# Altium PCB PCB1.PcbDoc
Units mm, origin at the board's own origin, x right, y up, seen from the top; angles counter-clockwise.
Board outline 100 x 80 mm, 2 copper layers (Top Layer, Bottom Layer); 38 components, 32 nets, 175 pads, 63 vias.
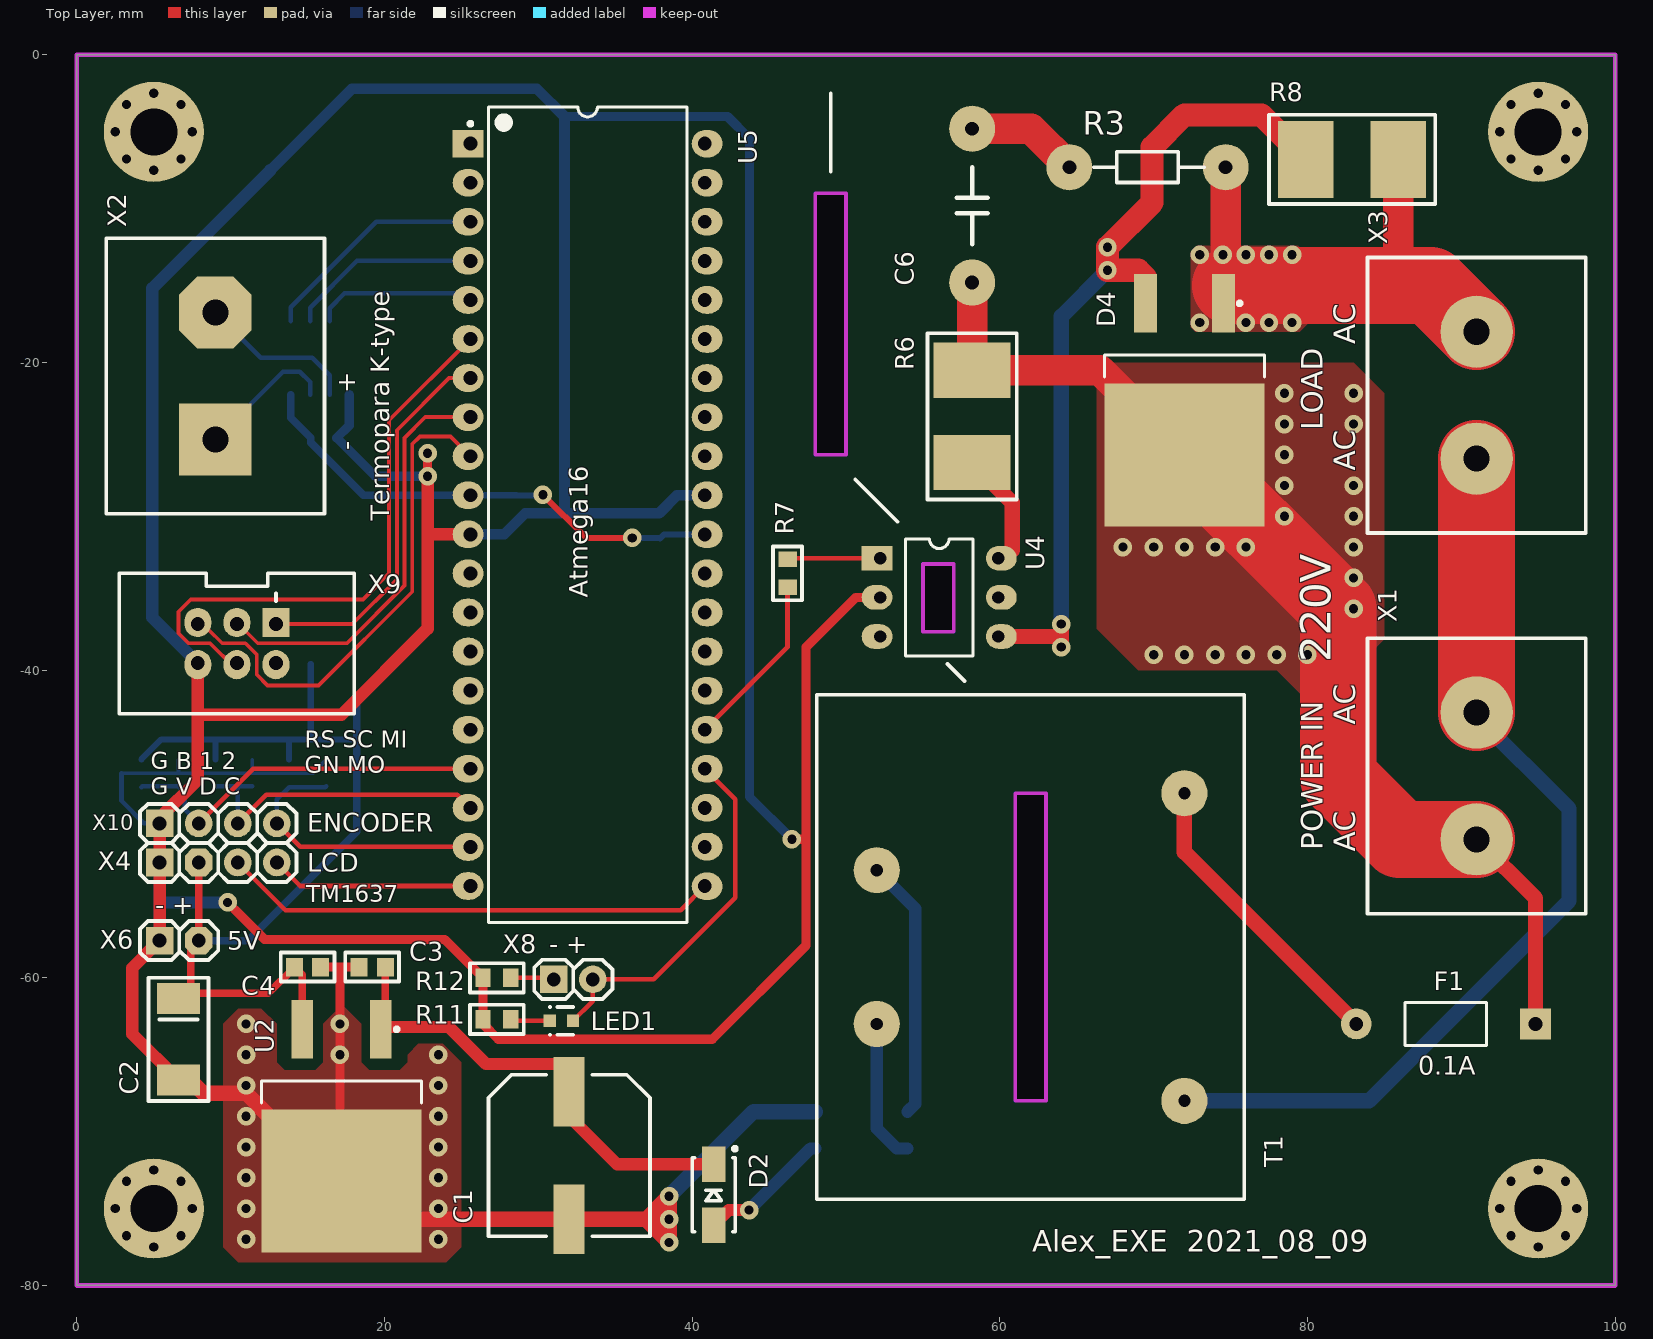
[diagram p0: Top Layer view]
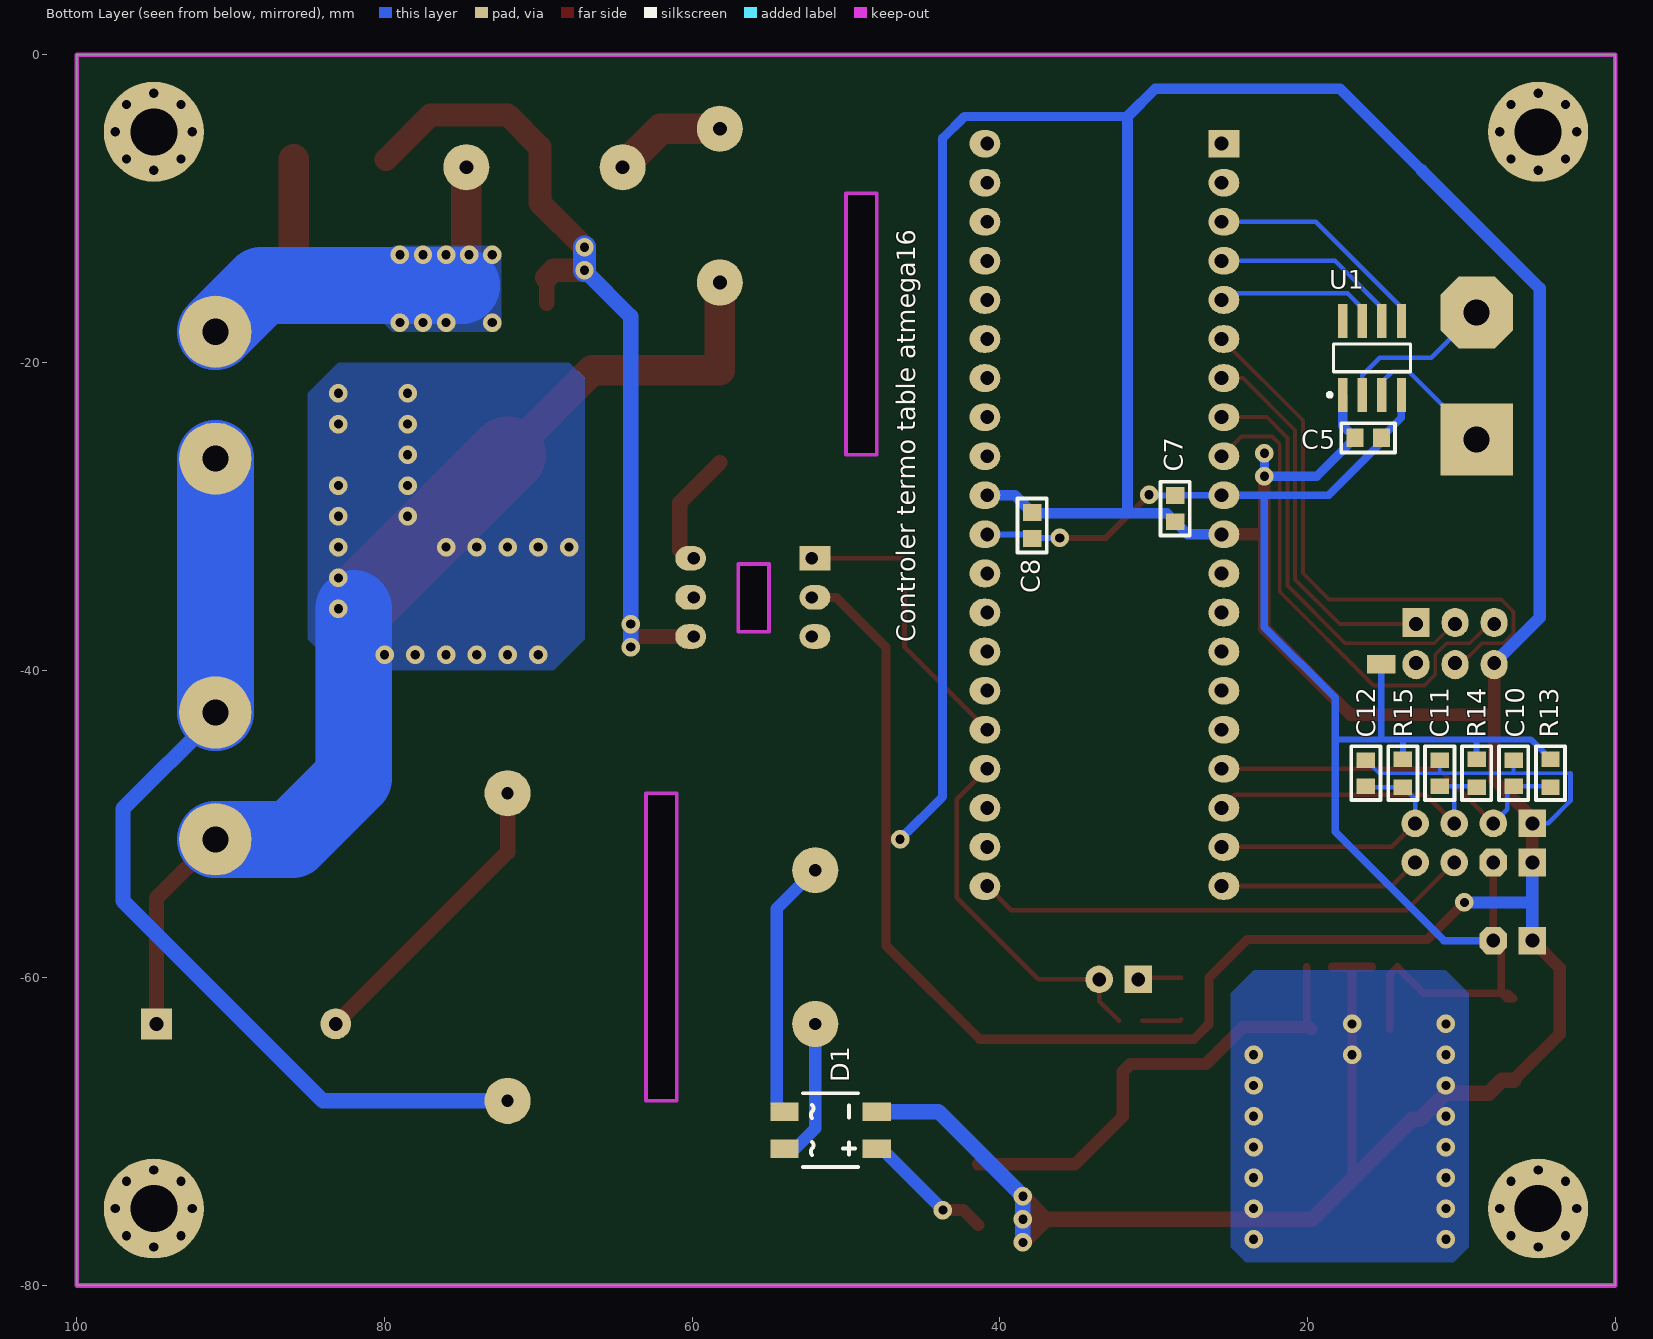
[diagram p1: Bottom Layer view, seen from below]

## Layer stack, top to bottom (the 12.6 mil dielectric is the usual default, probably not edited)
Top Solder: solder mask 0.0102, Solder Resist, Dk 3.5
Top Layer: signal copper 0.0356
Dielectric 1: dielectric 0.32, FR-4, Dk 4.8
Bottom Layer: signal copper 0.0356
Bottom Solder: solder mask 0.0102, Solder Resist, Dk 3.5

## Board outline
0,-80 0,0 100,0 100,-80
cut-out: 48,-9 50,-9 50,-26 48,-26
cut-out: 55,-33.1 57,-33.1 57,-37.5 55,-37.5
cut-out: 61,-48 63,-48 63,-68 61,-68

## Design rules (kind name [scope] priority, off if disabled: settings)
BoardOutlineClearance [All] p1: gap=0.8 ignorepadtopadclearanceinfootprint=FALSE
Clearance [All] p1: gap=0.25 ignorepadtopadclearanceinfootprint=FALSE
ComponentClearance ComponentClearance_x4_x9 [InComponent('X4') or InComponent('X9')] p1: gap=-1 collisioncheckmode=3 verticalgap=2540 showdistances=FALSE
ComponentClearance [All] p2: gap=0.254 collisioncheckmode=3 verticalgap=0.254 showdistances=FALSE
HoleSize HoleSize_via [IsVia] p1: absolutevalues=TRUE maxlimit=1 minlimit=0.5 maxpercent=80.000 minpercent=20.000
HoleSize [All] p2: absolutevalues=TRUE maxlimit=5 minlimit=0.6 maxpercent=80.000 minpercent=20.000
MinimumAnnularRing [All] p1: minimumring=0.3
MinimumSolderMaskSliver [All] p1: minsoldermaskwidth=0.24
PolygonConnect [All] p1: connectstyle=Direct reliefconductorwidth=0.254 reliefentries=4 polygonreliefangle="90 Angle" airgapwidth=0.254
RoomDefinition Sheet1 [InComponentClass('Sheet1')] p1: confinementstyle=ConfineIn formatcopy=TRUE lockcomponents=FALSE outline -58,-116 408,-116 408,80 -58,80
RoutingVias [All] p1: holewidth=0.6 width=1.2 viastyle="Through Hole" minholewidth=0.5 minwidth=1.2 maxholewidth=1 maxwidth=1.5
SilkToSilkClearance [All] p1: silktosilkclearance=0.24
SilkToSolderMaskClearance [IsPad] p1: minsilkscreentomaskgap=0.18 clearancetoexposedcopper=TRUE
SolderMaskExpansion [All] p1: expansion=0.08 istentingtop=FALSE
Width [All] p1: maxlimit=5 minlimit=0.25 preferedwidth=0.3
25 further rules are at their usual default settings.

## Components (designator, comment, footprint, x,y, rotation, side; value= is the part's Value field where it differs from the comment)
C1 "470uF" CAP-SMD-10.5 32,-75.7 r0 top
C2 "100uF" Tantal_C 6.6,-64 r270 top
C3 "0.1uF" CAP-0603#1 19.2,-59.3 r0 top
C4 "0.1uF" CAP-0603#1 15,-59.3 r180 top
C5 "0.1uF" CAP-0603#1 16.05,-24.9 r180 bottom
C6 "0.01uF" К73-17-630 58.2,-9.8 r270 top
C7 "0.1uF" CAP-0603#1 28.6,-29.5 r90 bottom
C8 "0.1uF" CAP-0603#1 37.9,-30.6 r270 bottom
C10 "0.1uF" CAP-0603#2 6.6,-46.7 r270 bottom
C11 "0.1uF" CAP-0603#2 11.4,-46.7 r270 bottom
C12 "0.1uF" CAP-0603#2 16.2,-46.7 r270 bottom
D1 "MB1S" MBS 51,-69.9 r270 bottom
D2 "SS16" SMA 41.4,-74.1 r270 top
D4 "BT136B-600E,118" TO-263_N#1 72,-22.45 r270 top
F1 "0.1A" PIN-W2/E2.8 89,-63 r180 top
LED1 "LED_LOAD" "LED0603 - red" 31.5,-62.8 r180 top
R3 "47" "resistor 0.125W 10.16mm" 69.6,-7.3 r0 top
R6 "360" res-2512 58.2,-23.5 r90 top
R7 "470" RES-0603 46.2,-33.7 r90 top
R8 "360" res-2512 82.9,-6.8 r0 top
R11 "1K" RES-0603 27.3,-62.7 r0 top
R12 "1K" RES-0603 27.3,-60 r180 top
R13 "47K" RES-0603 4.2,-46.7 r90 bottom
R14 "47K" RES-0603 9,-46.7 r90 bottom
R15 "47K" RES-0603 13.8,-46.7 r90 bottom
T1 "Trans" "BV EI Schema 1" 62,-58 r180 top
U1 "MAX31855EASA+" MAXM-S8+4_N 15.8,-19.7 r90 bottom
U2 "L7805ABD2T-TR" TO-263_N#2 17.2,-69.65 r270 top
U4 "MOC3061" DIP6 52.22,-32.73 r0 top
U5 "ATmega16-16PU" 40P6 33.2,-29.9 r0 top
X1 "KF35C-8.25-02P" KF35C-8.25-02P#1 91,-51 r90 top
X2 "KF35C-8.25-02P" KF35C-8.25-02P#2 9,-25 r90 top
X3 "KF35C-8.25-02P" KF35C-8.25-02P#1 91,-26.25 r90 top
X4 "PLS4" PLS4#1 5.38,-52.5 r0 top
X6 "PLS2" PLS2#1 5.38,-57.58 r0 top
X8 "PLS2" PLS2#2 31,-60.1 r0 top
X9 "IDC6M" IDC6M 12.94,-37 r180 top
X10 "PLS4" PLS4#2 5.38,-49.96 r0 top

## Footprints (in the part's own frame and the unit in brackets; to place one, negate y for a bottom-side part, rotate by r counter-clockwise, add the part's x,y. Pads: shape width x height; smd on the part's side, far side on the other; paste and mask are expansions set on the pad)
40P6 [mm] "40-Pin Ceramic Dual In-Line Package (CerDIP)"
  rect 2x1.8 hole 0.9 copper offset -0.15,0: 1(-7.62,24.13)
  oval 2x1.8 hole 0.9 copper offset -0.15,0: 2(-7.62,21.59) 3(-7.62,19.05) 4(-7.62,16.51) 5(-7.62,13.97) 6(-7.62,11.43) 7(-7.62,8.89) 8(-7.62,6.35) 9(-7.62,3.81) 10(-7.62,1.27) 11(-7.62,-1.27) 12(-7.62,-3.81) 13(-7.62,-6.35) 14(-7.62,-8.89) 15(-7.62,-11.43) 16(-7.62,-13.97) 17(-7.62,-16.51) 18(-7.62,-19.05) 19(-7.62,-21.59) 20(-7.62,-24.13)
  oval 2x1.8 hole 0.9 copper offset 0.15,-0.02: 21(7.62,-24.13)
  oval 2x1.8 hole 0.9 copper offset 0.15,0.02: 22(7.62,-21.59)
  oval 2x1.8 hole 0.9 copper offset 0.15,0: 23(7.62,-19.05) 24(7.62,-16.51) 25(7.62,-13.97) 26(7.62,-11.43) 27(7.62,-8.89) 28(7.62,-6.35) 29(7.62,-3.81) 30(7.62,-1.27) 31(7.62,1.27) 32(7.62,3.81) 33(7.62,6.35) 34(7.62,8.89) 35(7.62,11.43) 36(7.62,13.97) 37(7.62,16.51) 38(7.62,19.05) 39(7.62,21.59) 40(7.62,24.13)
  silkscreen extent -7.74,-26.5 6.45,26.5, body extent -7.05,-26.47 7.05,26.47, height 4.83
"BV EI Schema 1" [mm]
  round 3 hole 0.8: 1(-10,-10) 5(-10,10) 7(10,5) 9(10,-5)
  silkscreen extent -13.9,-16.4 13.9,16.4, body extent -13.9,-16.4 13.9,16.4, height 21.8
CAP-0603#1 [mm]
  rect 1.1x1.2 smd: 1(-0.85,0) 2(0.85,0)
  silkscreen extent -1.75,-0.95 1.75,0.95, body extent -0.85,-0.4 0.75,0.4, height 0.9
CAP-0603#2 [mm]
  rect 1x1.2 smd: 1(-0.85,0) 2(0.85,0)
  silkscreen extent -1.75,-0.95 1.75,0.95, body extent -0.85,-0.4 0.75,0.4, height 0.9
CAP-SMD-10.5 [mm]
  rect 2x4.5 smd: 1(0,8.3) 2(0,0)
  silkscreen extent -5.25,-1.1 5.25,9.4, body extent -5.25,-1.1 5.25,9.4, height 10.8
DIP6 [mm]
  rect 2x1.6 hole 0.8 copper offset -0.2,0: 1(0,0)
  oval 2x1.6 hole 0.8 copper offset -0.2,0: 2(0,-2.54) 3(0,-5.08)
  oval 2x1.6 hole 0.8 copper offset 0.2,0: 4(7.68,-5.08) 5(7.68,-2.54) 6(7.68,0)
  silkscreen extent 1.63,-6.35 6.05,1.27, body extent 1.45,-6.1 6.2,1, height 3.6
IDC6M [mm]
  rect 1.75x1.9 hole 0.9 copper offset 0,-0.1: 1(0,0)
  oval 1.75x1.9 hole 0.9 copper offset 0,0.1: 2(0,2.54) 4(2.54,2.54) 6(5.08,2.54)
  oval 1.75x1.9 hole 0.9 copper offset 0,-0.1: 3(2.54,0) 5(5.08,0)
  silkscreen extent -5.1,-3.3 10.18,5.84, body extent -5.1,-3.3 10.18,5.84, height 9
KF35C-8.25-02P#1 [mm]
  round 4.7 hole 1.7: 1(0,0) 2(8.25,0)
  silkscreen extent -4.83,-7.1 13.08,7.1, body extent -4.73,-7.05 12.97,7.05, height 15.1
KF35C-8.25-02P#2 [mm]
  rect 4.7x4.7 hole 1.7: 1(0,0)
  oct 4.7x4.7 hole 1.7: 2(8.25,0)
  silkscreen extent -4.83,-7.1 13.08,7.1, body extent -4.73,-7.05 12.97,7.05, height 15.1
"LED0603 - red" [mm]
  rect 0.8x0.8 smd: 1(-0.75,0) 2(0.75,0)
  silkscreen extent -0.75,-0.9 0.75,0.9, body extent -0.8,-0.4 0.8,0.4, height 0.8
MAXM-S8+4_N [mm] "SOIC, 8-Leads, Body 4.9x3.9mm, Pitch 1.27mm, IPC Medium Density"
  rect 2.2x0.6 smd: 1(-2.4,1.905) 2(-2.4,0.635) 3(-2.4,-0.635) 4(-2.4,-1.905) 5(2.4,-1.905) 6(2.4,-0.635) 7(2.4,0.635) 8(2.4,1.905)
  silkscreen extent -2.52,-2.5 0.9,2.88, body extent -2,-2.5 2,2.5, height 1.75
MBS [mm]
  rect 1.2x1.84 smd: 1(1.2,3) 2(-1.2,3) 3(-1.2,-3) 4(1.2,-3)
  silkscreen extent -2.4,-1.8 2.4,1.8, body extent -2.4,-3.5 2.4,3.5, height 3.05
PIN-W2/E2.8 [mm] "Thru-Hole; 2 Leads"
  rect 2x2 hole 0.9: 1(-5.825,0)
  round 2 hole 0.9: 2(5.825,0)
  silkscreen extent -2.65,-1.4 2.65,1.4
PLS2#1 [mm]
  rect 1.8x1.8 hole 0.9: 1(0,0)
  oct 1.8x1.8 hole 0.9: 2(2.54,0)
  silkscreen extent -1.27,-1.27 3.81,1.27, body extent -1.27,-1.27 3.81,1.27, height 8.5
PLS2#2 [mm]
  rect 1.8x1.8 hole 0.9: 1(0,0)
  round 1.8 hole 0.9: 2(2.54,0)
  silkscreen extent -1.27,-1.27 3.81,1.27, body extent -1.27,-1.27 3.81,1.27, height 8.5
PLS4#1 [mm]
  rect 1.8x1.8 hole 0.9: 1(0,0)
  oct 1.8x1.8 hole 0.9: 2(2.54,0)
  round 1.8 hole 0.9: 3(5.08,0) 4(7.62,0)
  silkscreen extent -1.27,-1.27 8.89,1.27, body extent -1.27,-1.27 8.89,1.27, height 8.5
PLS4#2 [mm]
  rect 1.8x1.8 hole 0.9: 1(0,0)
  round 1.8 hole 0.9: 2(2.54,0) 3(5.08,0) 4(7.62,0)
  silkscreen extent -1.27,-1.27 8.89,1.27, body extent -1.27,-1.27 8.89,1.27, height 8.5
RES-0603 [mm]
  rect 1x1.2 smd: 1(-0.9,0) 2(0.9,0)
  silkscreen extent -1.75,-0.95 1.75,0.95, body extent -0.85,-0.4 0.75,0.4, height 0.45
res-2512 [mm]
  rect 3.6x5 smd: 1(-3,0) 2(3,0)
  silkscreen extent -5.4,-2.9 5.4,2.9, body extent -3.2,-1.6 3.15,1.6, height 0.55
"resistor 0.125W 10.16mm" [mm] "resistor 0.125W 10.16mm"
  round 3 hole 0.9: 1(-5.08,0) 2(5.08,0)
  silkscreen extent -3.5,-1 3.68,1, body extent -5.18,-1 5.18,1, height 2.99
SMA [mm] "Molded Diode, 2-Leads, Body 4,50x2,60mm, IPC Medium Density"
  rect 2.3x1.55 smd: 1(-1.975,0) 2(1.975,0)
  silkscreen extent -3.12,-1.4 2.4,1.5, body extent -2.3,-1.35 2.3,1.35, height 2.1
Tantal_C [mm]
  rect 2x2.8 smd: 1(-2.65,0) 2(2.65,0)
  silkscreen extent -4,-1.95 4,1.95, body extent -3,-1.6 3,1.6, height 2.5
TO-263_N#1 [mm] "D2-PAK, 4-Leads, Body 9.2x10.2mm, Pitch 2.54mm, Lead Span 15.4mm, IPC Medium Density"
  rect 3.8x1.5 smd: 1(-6.3,2.54) 3(-6.3,-2.54)
  rect 9.3x10.4 smd: 4(3.55,0)
  silkscreen extent -6.42,-5.2 -1.5,5.2, body extent -2.95,-5.2 6.4,5.2, height 4.6
TO-263_N#2 [mm] "D2-PAK, 4-Leads, Body 9.2x10.2mm, Pitch 2.54mm, Lead Span 15.4mm, IPC Medium Density"
  rect 3.8x1.4 smd: 1(-6.3,2.54) 3(-6.3,-2.54)
  rect 9.3x10.4 smd: 4(3.55,0)
  silkscreen extent -6.42,-5.2 -1.5,5.2, body extent -2.95,-5.2 6.4,5.2, height 4.6
К73-17-630 [mm]
  round 3 hole 0.9: 1(-5,0) 2(5,0)
  silkscreen extent -2.5,-1 2.5,1, body extent -6,-3 6,3, height 12

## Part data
C1: library part "Cap Pol", "Polarized Capacitor (Axial)", Voltage=25V
C2: library part "Cap Pol", "Polarized Capacitor (Axial)", Voltage=16V
C3 C4 C5 C6 C7 C8 C10 C11 C12: library part Cap, "Capacitor", Voltage=25V
D1: library part Bridge1, "Full Wave Diode Bridge"
D2: library part "D Schottky", "Schottky Diode"
D4: library part BTA12-600C4G, "Triacs, Silicon Bidirectional Thyristor, 3-Pin TO-220, Pb-Free, Tube", Manufacturer="On Semiconductor"
F1: library part "Fuse 1", "Fuse"
LED1: library part LED0, "Typical INFRARED GaAs LED", Color=RED
R3 R6 R7 R8 R11 R12 R13 R14 R15: library part Res
T1: "Transformer"
U1: "Cold Junction Compensated Thermocouple to Digital Converter, 14 Bits Temperature Resolution, -40 to 125 degC, 8-Pin SOIC (S8+4), Pb-Free", Generic Part Number=MAX31855, Supplier Part Number 1=MAX31855EASA+-ND
U2: "Positive Voltage Regulator, 3-Pin D2PAK, Tape and Reel"
U4: library part MOC3021SM, "Опто транзистор x1 5.3kV 70V 0.05A"
U5: "8-bit AVR Microcontroller, 4.5-5.5V, 16KB Flash, 512 Bytes EEPROM, 1KB SRAM, 40-pin PDIP, Industrial Grade (-40°C to 85°C), Pb-Free"
X1 X2 X3: library part PLS2

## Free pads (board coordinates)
  round 6.5 hole 3.05 unplated: 1(5,-75) 1(5,-5) 1(95,-75) 1(95,-5)
  round 1.2 hole 0.6 mask+0.08: 2(2.5,-75) 2(2.5,-5) 2(3.232,-76.768) 2(3.232,-73.232) 2(3.232,-6.768) 2(3.232,-3.232) 2(5,-77.5) 2(5,-72.5) 2(5,-7.5) 2(5,-2.5) 2(6.768,-76.768) 2(6.768,-73.232) 2(6.768,-6.768) 2(6.768,-3.232) 2(7.5,-75) 2(7.5,-5) 2(92.5,-75) 2(92.5,-5) 2(93.232,-76.768) 2(93.232,-73.232) 2(93.232,-6.768) 2(93.232,-3.232) 2(95,-77.5) 2(95,-72.5) 2(95,-7.5) 2(95,-2.5) 2(96.768,-76.768) 2(96.768,-73.232) 2(96.768,-6.768) 2(96.768,-3.232) 2(97.5,-75) 2(97.5,-5)
  rect 1.84x1.2 smd far side: 11(15.2,-39.6)

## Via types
v1: diameter 1.2, hole 0.6, Top Layer to Bottom Layer, tented both sides, 63 vias

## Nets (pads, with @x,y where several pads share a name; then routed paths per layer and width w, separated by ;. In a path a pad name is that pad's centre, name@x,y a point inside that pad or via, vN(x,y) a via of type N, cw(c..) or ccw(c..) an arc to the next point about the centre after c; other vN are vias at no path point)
EN_1: C11.2 R14.1 U5.18 X10.3 | length 21.1
  Top Layer w0.3: X10.3 12.32,-48.1 24.73,-48.1 U5.18
  Bottom Layer w0.3: R14.1 9.05,-47.55 10.46,-47.55 ; X10.3 10.46,-47.55 ; C11.2 10.46,-47.55
EN_2: C12.2 R15.1 U5.19 X10.4 | length 18.3
  Top Layer w0.3: X10.4 14.53,-51.49 U5.19
  Bottom Layer w0.3: X10.4 13,-48.4 R15.1 16.15,-47.6 C12.2
EN_B: C10.2 R13.1 U5.17 X10.2 | length 24.5
  Top Layer w0.3: X10.2 11.47,-46.41 U5.17
  Bottom Layer w0.3: R13.1 4.25,-47.55 C10.2 7,-47.95 7,-49.04 X10.2
GND: C1.2 C2.2 C3.1 C4.1 C5.1 C7.1 C8.1 C10.1 C11.1 C12.1 D1.2 R11.1 R12.2 U1.1 U2.4 U4.2 U5.11 U5.31 X4.1 X6.1 X9.6 X10.1 | length 408.2
  Top Layer w0.6: 10.25,-55.55 12.2,-57.5 23.9,-57.5 R12.2 R11.1 26.4,-63 27.4,-64 41.3,-64 47.4,-57.9 47.4,-51 ; C4.1 17.1,-59.3 ; U2.4 17.1,-73.1 v1(17.1,-65) v1(17.1,-63) 17.1,-59.3 ; C3.1 17.1,-59.3 ; v1(22.8,-27.4) v1(22.8,-25.9) ; v1(46.485,-50.985) 47.385,-50.985 47.4,-51 ; U4.2 50.63,-35.27 47.4,-38.5 47.4,-51
  Top Layer w0.8: C2.2 3.6,-63.65 3.6,-59.36 X6.1 X4.1 X10.1 5.38,-49.62 7.86,-47.14 7.86,-42.9 ; X9.6 7.86,-42.9 ; v1(22.8,-27.4) 22.8,-31.17 ; U5.11 22.8,-31.17 ; 7.86,-42.9 17.2,-42.9 22.8,-37.3 22.8,-31.17
  Top Layer w1: C2.2 7.35,-66.65 8.2,-67.5 11,-67.5 12.7,-69.2 13.2,-69.2 U2.4@17.1,-73.1 ; U2.4 19.7,-75.7 C1.2 37,-75.7 ; 37,-75.7 v1(38.5,-74.2) v1(38.5,-75.7) ; 37,-75.7 v1(38.5,-77.2) v1(38.5,-75.7) ; 37,-75.7 v1(38.5,-75.7)
  Bottom Layer w0.25: 2.9,-46.7 6.6,-46.7 ; C10.1 6.6,-46.7 ; C11.1 11.4,-46.7 ; C12.1 15.35,-46.7 11.4,-46.7 ; 6.6,-46.7 11.4,-46.7
  Bottom Layer w0.3: 2.9,-46.7 2.9,-48.5 4.36,-49.96 X10.1
  Bottom Layer w0.6: U1.1 17.705,-24.095 C5.1 19.4,-27.4 v1(22.8,-27.4) v1(22.8,-25.9) ; 31.7,-4 42.3,-4 43.72,-5.42 43.72,-30.98 43.72,-48.22 v1(46.485,-50.985)
  Bottom Layer w0.7: 12.58,-7.5 17.88,-2.2 29.9,-2.2 31.7,-4 31.7,-29.8 ; U5.11 27.78,-31.17 C7.1 29.15,-29.8 31.7,-29.8 ; U5.31 39.02,-28.63 C8.1 37.85,-29.8 31.7,-29.8
  Bottom Layer w0.8: X6.1 5.38,-55.1 ; X4.1 5.38,-55.1 ; X9.6 4.9,-36.58 4.9,-15.18 12.58,-7.5 ; v1(9.8,-55.1) 5.38,-55.1
  Bottom Layer w1: v1(38.5,-77.2) v1(38.5,-75.7) v1(38.5,-74.2) 44,-68.7 D1.2
  other v1: 11,-77 23.5,-77 11,-75 23.5,-75 11,-73 23.5,-73 11,-71 23.5,-71 11,-69 23.5,-69 11,-67 23.5,-67 11,-65 23.5,-65 11,-63
L_CLK: U5.20 X4.4 | length 13.2
  Top Layer w0.3: X4.4 14.53,-54.03 U5.20
L_DIO: U5.21 X4.3 | length 32.3
  Top Layer w0.3: X4.3 13.56,-55.6 39.25,-55.6 U5.21
LED_LOAD: LED1.1 U5.24 X8.2 | length 23.9
  Top Layer w0.3: LED1.1 33.54,-61.51 X8.2 37.5,-60.1 42.799,-54.801 42.799,-52.901 42.8,-52.9 42.8,-48.39 U5.24
LOAD_ON: R7.1 U5.25 | length 11.5
  Top Layer w0.3: U5.25 46.2,-38.49 R7.1
MISO: U5.7 X9.1 | length 24.9
  Top Layer w0.25: X9.1 17.9,-37 20.8,-34.1 20.8,-24.4 24.19,-21.01 U5.7
MOSI: U5.6 X9.4 | length 38.3
  Top Layer w0.25: X9.4 10.17,-39.77 8.65,-38.25 7.25,-38.25 6.6,-37.6 6.6,-36.2 7.4,-35.4 18.6,-35.4 20.3,-33.7 20.3,-23.75 U5.6
NetC1_1: C1.1 C3.2 D2.1 U2.1 | length 31.3
  Top Layer w0.5: U2.1 20.05,-63.04 C3.2
  Top Layer w0.8: U2.1 19.89,-63.2 24.2,-63.2 26.6,-65.6 31.5,-65.6 32,-66.1 C1.1 32,-69 35.125,-72.125 D2.1
NetC6_1: C6.1 R3.1 | length 7.4
  Top Layer w2: C6.1 62.02,-4.8 R3.1
NetC6_2: C6.2 D4.4 F1.1 R6.2 X1.1 | length 93.4
  Top Layer w1: D4.4 D4.4@72,-25.4 ; X1.1 94.825,-54.825 F1.1
  Top Layer w2: C6.2 R6.2 66.5,-20.5 D4.4
  Top Layer w5: D4.4 81.5,-35.5 82,-36 82,-47 86,-51 X1.1
  Bottom Layer w5: 82,-36 82,-47 86,-51 X1.1
  other v1: 70,-39 72,-39 74,-39 76,-39 78,-39 80,-39 83,-36 83,-34 68,-32 70,-32 72,-32 74,-32 76,-32 83,-32 78.5,-30 83,-30 78.5,-28 83,-28 78.5,-26 78.5,-24 83,-24 78.5,-22 83,-22
NetD1_1: D1.1 D2.2 | length 8.7
  Top Layer w0.8: D2.2 42.375,-75.1 v1(43.7,-75.1)
  Bottom Layer w0.8: v1(43.7,-75.1) 47.7,-71.1 D1.1
NetD1_3: D1.3 T1.9 | length 16.9
  Bottom Layer w0.8: T1.9 54.5,-55.5 54.5,-60.4 54.5,-68.2 D1.3
NetD1_4: D1.4 T1.7 | length 9.4
  Bottom Layer w0.6: D1.4 D1.4@54.05,-71.15
  Bottom Layer w0.8: T1.7 52,-69.8 53.3,-71.1 D1.4
NetD4_1: D4.1 R3.2 R8.2 X3.2 | length 51.4
  Top Layer w1: 85.9,-12.9 88,-15
  Top Layer w2: R3.2 74.68,-14.68 D4.1@75,-15 ; 85.9,-12.9 R8.2
  Top Layer w5: D4.1@75,-15 88,-15 X3.2
  Bottom Layer w5: 75,-15 88,-15 X3.2
  other v1: 73,-17.4 76,-17.4 77.5,-17.4 79,-17.4 73,-13 74.5,-13 76,-13 77.5,-13 79,-13
NetD4_3: D4.3 R8.1 U4.4 | length 58.5
  Top Layer w1: U4.4 63.94,-37.81 64,-37.75 ; v1(64,-38.5) 64,-37.75 ; v1(64,-37) 64,-37.75 ; D4.3 D4.3@69.46,-14.46
  Top Layer w1.5: D4.3@69.46,-14.46 69,-14 v1(67,-14) v1(67,-12.5) 69.9,-9.6 69.9,-6 72,-3.9 77,-3.9 R8.1
  Bottom Layer w1: v1(64,-38.5) v1(64,-37) 64,-17 v1(67,-14)
  Bottom Layer w1.5: v1(67,-14) v1(67,-12.5)
NetF1_2: F1.2 T1.1 | length 19.6
  Top Layer w1: T1.1 72,-51.825 F1.2
NetLED1_2: LED1.2 R11.2 | length 2.6
  Top Layer w0.3: R11.2 28.3,-62.8 LED1.2
NetR6_1: R6.1 U4.6 | length 7.9
  Top Layer w1: R6.1 60.8,-29.1 60.8,-32.2 60.27,-32.73 U4.6
NetR7_2: R7.2 U4.1 | length 6
  Top Layer w0.3: R7.2 46.27,-32.73 U4.1
NetR12_1: R12.1 X8.1 | length 2.8
  Top Layer w0.3: R12.1 30.9,-60 X8.1
NetT1_5: T1.5 X1.2 X3.1 | length 78.1
  Top Layer w5: X1.2 X3.1
  Bottom Layer w1: T1.5 84,-68 97,-55 97,-49 91,-43 X1.2
  Bottom Layer w5: X1.2 X3.1
NetU1_2: U1.2 X2.2 | length 10.4
  Bottom Layer w0.3: X2.2 11.95,-19.7 15.3,-19.7 16.435,-20.835 U1.2
NetU1_3: U1.3 X2.1 | length 9.1
  Bottom Layer w0.3: X2.1 13.4,-20.6 14.5,-20.6 15.165,-21.265 U1.3
RST: U5.9 X9.5 | length 33
  Top Layer w0.25: X9.5 8.26,-37.4 8.6,-37.4 9.45,-38.25 10.95,-38.25 11.69,-38.99 11.69,-40.29 12.4,-41 15.7,-41 21.8,-34.9 21.8,-25.3 22.3,-24.8 24.29,-24.8 U5.9
SCK: U5.8 X9.3 | length 27.4
  Top Layer w0.25: X9.3 10.9,-37.5 11.007,-37.5 11.757,-38.25 17.55,-38.25 21.3,-34.5 21.3,-24.9 22.65,-23.55 U5.8
t_CS: U1.6 U5.4 | length 12.5
  Bottom Layer w0.3: U1.6 15.165,-16.435 18.21,-13.39 U5.4
t_SCK: U1.5 U5.3 | length 14.9
  Bottom Layer w0.3: U1.5 13.895,-16.405 19.45,-10.85 U5.3
t_SO: U1.7 U5.5 | length 10.6
  Bottom Layer w0.3: U1.7 16.435,-16.465 17.4,-15.5 25.15,-15.5 U5.5
VDD: C2.1 C4.2 C5.2 C7.2 C8.2 pad.11 R13.2 R14.2 R15.2 U1.4 U2.3 U5.10 U5.30 X4.2 X6.2 | length 113.4
  Top Layer w0.4: v1(30.3,-28.6) 33.1,-31.4 v1(36.1,-31.4)
  Top Layer w0.5: X4.2 X6.2 7.4,-58.1 C2.1@7.4,-61 ; U2.3 14.66,-59.81 C4.2 12.45,-61 C2.1@7.4,-61 ; C2.1@7.4,-61 7.05,-61.35 C2.1 6.95,-61 C2.1@7.4,-61
  Bottom Layer w0.4: R13.2 5.5,-44.5 9,-44.5 ; R14.2 9,-44.5 ; R15.2 13.8,-44.5 ; pad.11 15.2,-44.5 ; 18.2,-44.5 15.2,-44.5 ; U5.10 28.58,-28.63 C7.2 30.25,-28.65 v1(30.3,-28.6) ; v1(36.1,-31.4) 37.85,-31.4 C8.2 38.18,-31.17 U5.30 ; 9,-44.5 13.8,-44.5 ; 13.8,-44.5 15.2,-44.5
  Bottom Layer w0.5: X6.2 11.12,-57.58 18.2,-50.5 18.2,-44.5 18.2,-41.8 22.8,-37.2 22.8,-28.63 ; U1.4 13.895,-23.595 C5.2 15.2,-25.2 18.63,-28.63 U5.10
pads on no net: U1.8 U4.3 U4.5 U5.1 U5.2 U5.12 U5.13 U5.14 U5.15 U5.16 U5.22 U5.23 U5.26 U5.27 U5.28 U5.29 U5.32 U5.33 U5.34 U5.35 U5.36 U5.37 U5.38 U5.39 U5.40 X9.2

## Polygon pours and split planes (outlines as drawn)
NetC6_2 on Bottom Layer "Top Layer-No Net" (solid, pour order 0): 67,-21 68,-20 83,-20 85,-22 85,-38 83,-40 69,-40 67,-38
NetD4_1 on Bottom Layer "Top Layer-No Net" (solid, pour order 4): 72.4,-12.8 72.8,-12.4 79.4,-12.4 80.5,-13.5 80.5,-17 79.5,-18 72.7,-18 72.4,-17.7
GND on Bottom Layer "Top Layer-No Net" (solid, pour order 10): 11,-59.5 23.5,-59.5 25,-61 25,-77.5 24,-78.5 10.5,-78.5 9.5,-77.5 9.5,-61
NetC6_2 on Top Layer "Top Layer-No Net" (solid, pour order 2): 66.3,-20.2 67.1,-20 83,-20 85,-22 85,-38 80.5,-42.5 78,-40 69,-40 66.3,-37.3
NetD4_1 on Top Layer "Top Layer-No Net" (solid, pour order 6): 72.8,-12.4 72.4,-12.8 72.4,-17.7 72.7,-18 79.5,-18 80.4,-17.1 80.4,-13.4 79.4,-12.4
GND on Top Layer "Top Layer-No Net" (solid, pour order 12): 9.5,-63 10.5,-62 12,-62 13,-63 13,-65.5 13.5,-66 15.5,-66 16,-65.5 16,-63 17.2,-61.8 17.3,-61.8 18.5,-63 18.5,-65.5 19,-66 21,-66 21.5,-65.5 21.5,-65 22.2,-64.3 23.8,-64.3 25,-65.5 25,-77.5 24,-78.5 10.5,-78.5 9.5,-77.5

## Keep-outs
Keep-Out Layer:
  lines w0.24: 48,-26 50,-26 50,-9 48,-9 48,-26 ; 55,-37.5 57,-37.5 57,-33.1 55,-33.1 55,-37.5 ; 61,-68 63,-68 63,-48 61,-48 61,-68
  lines w0.3: 0,-80 100,-80 100,0 0,0 0,-80

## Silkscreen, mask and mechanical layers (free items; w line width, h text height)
Top Overlay:
  lines w0.24: 49,-7.6 49,-2.5 ; 50.6,-27.6 53.35,-30.35 ; 56.6,-39.6 57.7,-40.7
  text "AC" at 83.1,-18.8 h1.4 r90
  text "LOAD" at 81,-24.4 h1.4 r90
  text "-      +" at 18.1,-25.7 h1.2 r90
  text "AC" at 83.1,-27.05 h1.4 r90
  text "Termopara K-type" at 20.3,-30.3 h1.2 r90
  text "Atmega16" at 33.2,-35.3 h1.2 r90
  text "220V" at 81.5,-39.5 h2 r90
  text "AC" at 83.1,-43.55 h1.4 r90
  text "RS SC MI / GN MO" at 14.8,-46.7 h1.1
  text "G B 1 2 / G V D C" at 4.8,-48.1 h1.1
  text "ENCODER" at 14.96,-50.5 h1.2
  text "POWER IN" at 81,-51.7 h1.4 r90
  text "AC" at 83.1,-51.8 h1.4 r90
  text "LCD" at 14.96,-53.1 h1.2
  text "TM1637" at 14.9,-55.1 h1.1
  text "- +" at 5.08,-55.88 h1.2
  text "5V" at 9.78,-58.18 h1.2
  text "- +" at 30.7,-58.4 h1.2
  text "0.1A" at 87.2,-66.3 h1.2
  text "Alex_EXE  2021_08_09" at 62.1,-77.8 h1.4
Bottom Overlay:
  text "Controler termo table atmega16" at 45.5,-38.2 h1.2 r270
